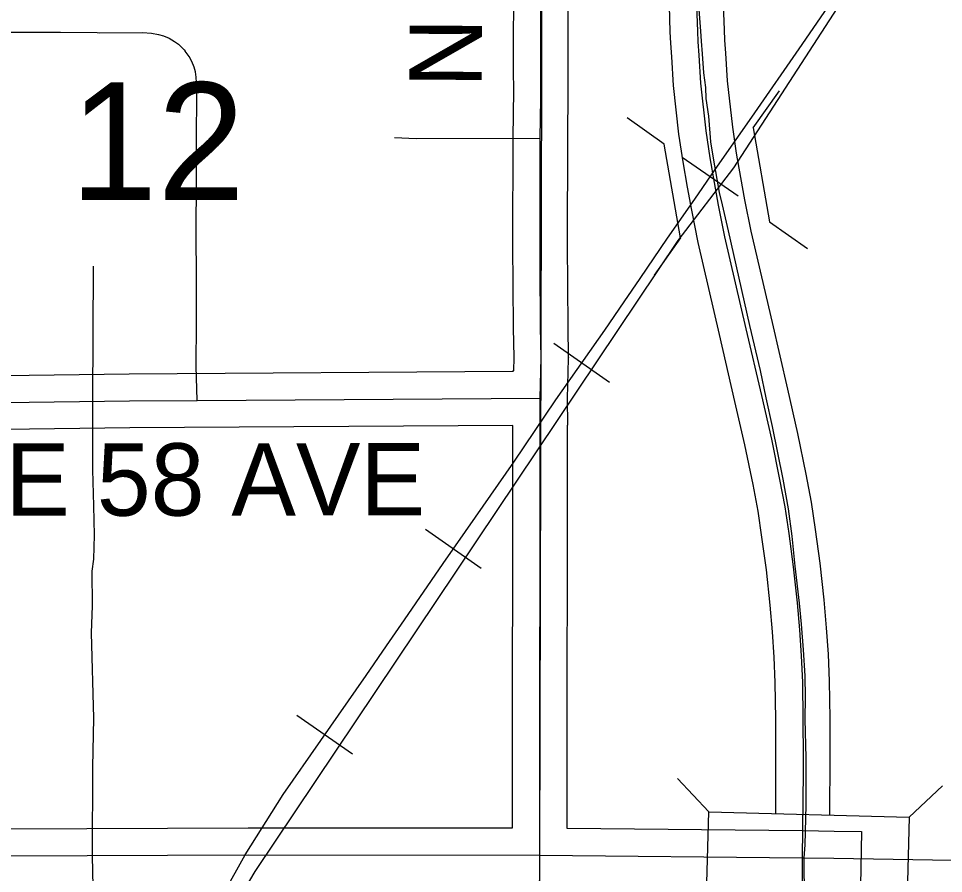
# Model space of a CAD drawing. Extents: x -1403959 to 81668, y -1400582 to 11018.
# Drawn here: x 7328.3 to 7427.2, y 8716.6 to 8808.1 of the extents above; entities that cross this region are included whole.
import ezdxf

# ---------------------------------------------------------------- set-up
doc = ezdxf.new("R2010")
doc.units = 0
for name, color, linetype in [('tdCiAirportTxt', 7, 'Continuous'), ('tdCiCityCartoShort', 7, 'Continuous'), ('tdCiCityStreetTxt', 7, 'Continuous'), ('tdCiCoBndryTxt', 7, 'Continuous'), ('tdCiRRCL', 7, 'Continuous'), ('tdCiSectLine', 7, 'Continuous'), ('tdCiSectNmbr', 7, 'Continuous'), ('tdCiUABTitleFrame', 7, 'Continuous'), ('tdCoClipBndry', 7, 'Continuous'), ('tdCoSecRteBand', 7, 'Continuous'), ('tdCoSectLinePart', 7, 'Continuous'), ('tdCoSectNmbr', 7, 'Continuous'), ('tdCoSurfEarth', 7, 'Continuous')]:
    doc.layers.add(name, color=color, linetype=linetype)

msp = doc.modelspace()

# ---------------------------------------------------------------- linework, layer by layer
at = {"layer": 'tdCiAirportTxt'}
for points in [[(7409.253, 8722.994), (7409.27, 8729.022), (7409.255, 8733.105), (7409.206, 8737.011), (7409.089, 8739.721), (7408.912, 8742.451), (7408.67, 8745.293), (7408.255, 8749.071), (7407.765, 8752.56), (7407.365, 8755.354), (7406.826, 8758.192), (7405.961, 8762.446), (7404.889, 8767.084), (7403.238, 8774.241), (7400.949, 8784.103), (7400.264, 8787.569), (7399.805, 8790.03), (7399.342, 8792.729), (7398.906, 8795.691), (7398.322, 8800.909), (7398.138, 8803.974), (7398.029, 8805.414), (7397.979, 8806.622), (7397.881, 8809.431)], [(7415.056, 8722.836), (7415.074, 8729.024), (7415.059, 8733.152), (7415.008, 8737.173), (7414.885, 8740.034), (7414.7, 8742.885), (7414.446, 8745.857), (7414.014, 8749.792), (7413.511, 8753.374), (7413.092, 8756.307), (7412.521, 8759.312), (7411.633, 8763.678), (7410.543, 8768.39), (7408.892, 8775.549), (7406.624, 8785.322), (7405.964, 8788.664), (7405.518, 8791.053), (7405.074, 8793.642), (7404.663, 8796.437), (7404.106, 8801.407), (7403.928, 8804.366), (7403.824, 8805.753), (7403.778, 8806.844), (7403.684, 8809.532)]]:
    msp.add_lwpolyline(points, dxfattribs=at)
at = {"layer": 'tdCiCityCartoShort'}
for points in [[(7400.782, 8809.459), (7400.878, 8806.711), (7400.926, 8805.561), (7401.033, 8804.148), (7401.214, 8801.137), (7401.784, 8796.042), (7402.208, 8793.165), (7402.661, 8790.521), (7403.114, 8788.096), (7403.786, 8784.692), (7406.065, 8774.875), (7407.716, 8767.716), (7408.797, 8763.041), (7409.673, 8758.732), (7410.228, 8755.81), (7410.637, 8752.946), (7411.134, 8749.411), (7411.558, 8745.554), (7411.806, 8742.647), (7411.987, 8739.856), (7412.107, 8737.07), (7412.157, 8733.106), (7412.172, 8729.001), (7412.154, 8722.822)], [(7412.087, 8710.816), (7412.154, 8722.83)]]:
    msp.add_lwpolyline(points, dxfattribs=at)
at = {"layer": 'tdCiCityStreetTxt'}
for p, q in [((7402.098, 8723.189), (7398.748, 8726.73)), ((7423.536, 8722.604), (7427.077, 8725.957)), ((7401.833, 8713.448), (7402.098, 8723.189)), ((7402.098, 8723.189), (7423.536, 8722.604)), ((7423.536, 8722.604), (7423.27, 8712.863))]:
    msp.add_line(p, q, dxfattribs=at)
at = {"layer": 'tdCiCoBndryTxt'}
for points in [[(7384.125, 8799.454), (7384.136, 8800.348), (7384.122, 8802.529), (7384.136, 8814.184), (7384.149, 8815.842)], [(7384.067, 8789.646), (7384.076, 8795.251), (7384.125, 8799.454)], [(7384.102, 8775.037), (7384.07, 8781.596), (7384.059, 8783.908), (7384.067, 8789.646)], [(7384.174, 8771.777), (7384.102, 8775.037)], [(7384.05, 8767.445), (7384.174, 8771.777)], [(7314.56, 8766.881), (7320.741, 8766.932), (7326.761, 8766.981), (7340.144, 8767.154), (7347.37, 8767.202), (7384.05, 8767.445)], [(7383.863, 8691.595), (7384.016, 8718.554), (7384.05, 8767.445)], [(7294.379, 8718.273), (7326.99, 8718.463), (7352.842, 8718.586)], [(7352.842, 8718.586), (7384.016, 8718.554)], [(7384.016, 8718.554), (7412.091, 8718.274), (7412.188, 8718.272)], [(7412.188, 8718.272), (7415.463, 8718.216)]]:
    msp.add_lwpolyline(points, dxfattribs=at)
at = {"layer": 'tdCiRRCL'}
msp.add_lwpolyline([(7412.335, 8713.816), (7412.311, 8718.27), (7412.394, 8719.641), (7412.514, 8723.904), (7412.514, 8727.811), (7412.493, 8728.956), (7412.411, 8733.088), (7412.452, 8735.4), (7412.391, 8737.731), (7412.233, 8740.501), (7412.023, 8743.254), (7411.798, 8745.525), (7411.348, 8749.472), (7411, 8752.663), (7410.632, 8755.609), (7410.039, 8758.759), (7408.914, 8764.404), (7408.218, 8767.493), (7407.625, 8770.418), (7406.5, 8775.204), (7404.209, 8785.35), (7403.557, 8788.124), (7403.248, 8789.441), (7402.61, 8793.13), (7402.307, 8794.882), (7402.102, 8797.623), (7401.816, 8799.504), (7401.775, 8800.691), (7401.57, 8802.245), (7401.407, 8804.291), (7401.325, 8805.641), (7401.243, 8806.704), (7401.039, 8809.486)], dxfattribs=at)
at = {"layer": 'tdCiSectLine'}
for points in [[(7326.73, 8769.883), (7340.107, 8770.055), (7340.125, 8770.056), (7381.15, 8770.327), (7381.15, 8770.349), (7381.23, 8770.349), (7381.272, 8771.787), (7381.201, 8774.973), (7381.2, 8775.023), (7381.157, 8783.894), (7381.157, 8783.908), (7381.157, 8783.912), (7381.174, 8795.255), (7381.174, 8795.285), (7381.234, 8800.355), (7381.22, 8802.511), (7381.22, 8802.529), (7381.22, 8802.533), (7381.233, 8813.126)], [(7387.036, 8812.943), (7387.024, 8802.537), (7387.038, 8800.366), (7387.038, 8800.348), (7387.037, 8800.314), (7386.978, 8795.231), (7386.96, 8783.913), (7387.004, 8775.076), (7387.075, 8771.841), (7387.076, 8771.777), (7387.075, 8771.694), (7386.952, 8767.413), (7386.971, 8764.562), (7386.95, 8764.562), (7386.92, 8721.453), (7386.921, 8721.453), (7386.921, 8721.44), (7386.934, 8721.44), (7386.934, 8721.427), (7412.12, 8721.175), (7412.14, 8721.175), (7415.512, 8721.118), (7418.413, 8721.069), (7418.315, 8715.266)], [(7326.976, 8721.365), (7352.829, 8721.487), (7352.842, 8721.487), (7352.845, 8721.487), (7381.116, 8721.459), (7381.146, 8764.524), (7340.173, 8764.252), (7326.798, 8764.08)]]:
    msp.add_lwpolyline(points, dxfattribs=at)
at = {"layer": 'tdCiSectNmbr'}
msp.add_lwpolyline([(7415.463, 8718.216), (7445.057, 8717.715), (7460.953, 8717.481)], dxfattribs=at)
at = {"layer": 'tdCiUABTitleFrame'}
for points in [[(7320.782, 8806.629), (7323.642, 8806.604), (7327.998, 8806.604), (7332.786, 8806.596), (7336.708, 8806.55)], [(7336.708, 8806.55), (7336.963, 8806.547), (7341.539, 8806.564), (7342.491, 8806.507), (7343.248, 8806.368), (7343.769, 8806.213), (7344.38, 8805.969), (7344.966, 8805.595), (7345.398, 8805.318), (7345.981, 8804.699)], [(7345.981, 8804.699), (7346.093, 8804.581)], [(7347.37, 8767.202), (7347.295, 8770.869), (7347.319, 8775.493), (7347.311, 8779.972), (7347.295, 8785.419), (7347.311, 8790.442), (7347.328, 8795.034), (7347.352, 8800.025), (7347.319, 8801.222), (7347.279, 8801.792), (7347.197, 8802.346), (7347.075, 8802.843), (7346.831, 8803.453), (7346.53, 8803.999), (7346.093, 8804.581)], [(7368.501, 8795.314), (7370.814, 8795.231), (7384.003, 8795.25), (7384.076, 8795.251)]]:
    msp.add_lwpolyline(points, dxfattribs=at)
at = {"layer": 'tdCoClipBndry'}
msp.add_lwpolyline([(7384.127, 8916.677), (7383.88, 8864.542), (7384.247, 8815.842), (7383.983, 8718.555), (7383.532, 8621.696), (7383.596, 8572.531)], dxfattribs=at)
at = {"layer": 'tdCoSecRteBand'}
for p, q in [((7405.226, 8789.052), (7399.258, 8793.177)), ((7404.754, 8792.082), (7398.778, 8784.312)), ((7391.487, 8769.131), (7385.54, 8773.284)), ((7377.742, 8749.234), (7371.796, 8753.39)), ((7363.994, 8729.343), (7358.046, 8733.496))]:
    msp.add_line(p, q, dxfattribs=at)
for points in [[(7531.389, 8864.087), (7475.165, 8854.019), (7447.352, 8846.617), (7431.89, 8832.005), (7427.139, 8825.911), (7426.068, 8824.998), (7404.754, 8792.082)], [(7350.223, 8714.48), (7352.531, 8718.563), (7356.588, 8725.028), (7360.594, 8730.81), (7365.463, 8737.783), (7367.633, 8740.951), (7369.545, 8743.741), (7373.678, 8749.751), (7377.152, 8754.721), (7381.234, 8760.603), (7385.748, 8767.247), (7390.971, 8774.727), (7393.058, 8777.761), (7394.774, 8780.255), (7397.69, 8784.565), (7400.606, 8788.749), (7402.785, 8791.902), (7406.692, 8797.522), (7412.067, 8805.281), (7418.026, 8813.978)], [(7350.223, 8714.48), (7352.531, 8718.563), (7356.588, 8725.028), (7360.594, 8730.81), (7365.463, 8737.783), (7367.633, 8740.951), (7369.545, 8743.741), (7373.678, 8749.751), (7377.152, 8754.721), (7381.234, 8760.603), (7385.748, 8767.247), (7390.971, 8774.727), (7393.058, 8777.761), (7394.774, 8780.255), (7397.69, 8784.565), (7400.606, 8788.749), (7402.785, 8791.902), (7406.692, 8797.522), (7412.067, 8805.281), (7418.026, 8813.978)], [(7398.778, 8784.312), (7353.548, 8716.807), (7347.873, 8707.205), (7342.952, 8694.395), (7340.78, 8681.728), (7339.837, 8671.349), (7339.057, 8665.55)], [(7336.269, 8781.553), (7336.209, 8767.126), (7336.209, 8759.763), (7336.309, 8755.917), (7336.359, 8752.769), (7336.309, 8750.221), (7336.109, 8748.921), (7336.159, 8745.224), (7336.059, 8742.34), (7336.309, 8733.196), (7336.209, 8727.974), (7336.159, 8718.48), (7336.259, 8713.508)]]:
    msp.add_lwpolyline(points, dxfattribs=at)
at = {"layer": 'tdCoSurfEarth'}
for p, q in [((7406.853, 8796.354), (7409.663, 8800.339)), ((7397.336, 8794.616), (7393.351, 8797.426)), ((7406.853, 8796.354), (7408.589, 8786.313)), ((7399.069, 8784.595), (7397.336, 8794.616)), ((7408.589, 8786.313), (7412.656, 8783.447)), ((7399.069, 8784.595), (7396.258, 8780.612))]:
    msp.add_line(p, q, dxfattribs=at)

# ---------------------------------------------------------------- texts
at = {"layer": 'tdCoSectLinePart'}
msp.add_text('12', height=12.5746, rotation=359.99644, dxfattribs=at).set_placement((7333.79, 8788.644))
at = {"layer": 'tdCoSectNmbr'}
for s, rotation, p in [('NE 22 ST', 89.79061, (7377.813, 8800.642)), ('NE 58 AVE', 0.06266, (7319.409, 8754.844))]:
    msp.add_text(s, height=7.7382, rotation=rotation, dxfattribs=at).set_placement(p)

doc.saveas('drawing.dxf')
